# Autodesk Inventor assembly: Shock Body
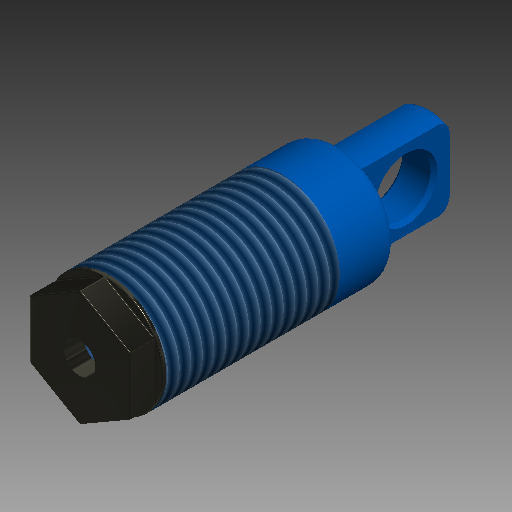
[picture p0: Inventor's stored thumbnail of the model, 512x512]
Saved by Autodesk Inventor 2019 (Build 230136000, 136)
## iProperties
Shininess: 50.0
Compacted: True
Length Units: 11272
Angle Units: 11279
Time Units: 11290
Mass Units: 11286
Length Display Precision: 4
Angle Display Precision: 2
Company: Autodesk
Created: 2000-03
Part Number: Shock Body
Project: Inventor Samples
Document SubType Name: Assembly
Designer: Autodesk, Inc.
Mass: 2.25365 g
Surface Area: 36.8123 cm^2
Volume: 2.00486 cm^3
Density: 1.12409 g/cm^3
Density: 0.0
Volumn: 0.0
Area: 0.0
PropertySet Name: Model Information
Control State: 0
Master: False
Checked Out: False
Checked Out Date: 2018-05-30
Last Check In Date: 2018-05-30
Title: 1.3 SHOCK
Author: Autodesk, Inc.
Revision Number: A
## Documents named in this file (3)
- C:\Users\itools\Desktop\autodesk_inventor_2018_samples\Models\Assemblies\Suspension\Components\Shock Body.iam
- C:\Users\itools\Desktop\autodesk_inventor_2018_samples\Models\Assemblies\Suspension\Components\Shock Body 1.3 Length.ipt
- C:\Users\itools\Desktop\autodesk_inventor_2018_samples\Models\Assemblies\Suspension\Components\Shock Cartridge.iam
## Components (2 placed, 2 different names)
1. Shock Body — Mate:1, Mate Extension, Angle:1
2. Shock Cartridge:1 [sub-assembly] — Mate:1, Mate Extension, Angle:1
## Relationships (3: Mate 2, Angle 1)
- Mate:1: Shock Body ↔ Shock Cartridge:1
- Mate Extension: Shock Body ↔ Shock Cartridge:1
- Angle:1: Shock Body ↔ Shock Cartridge:1
